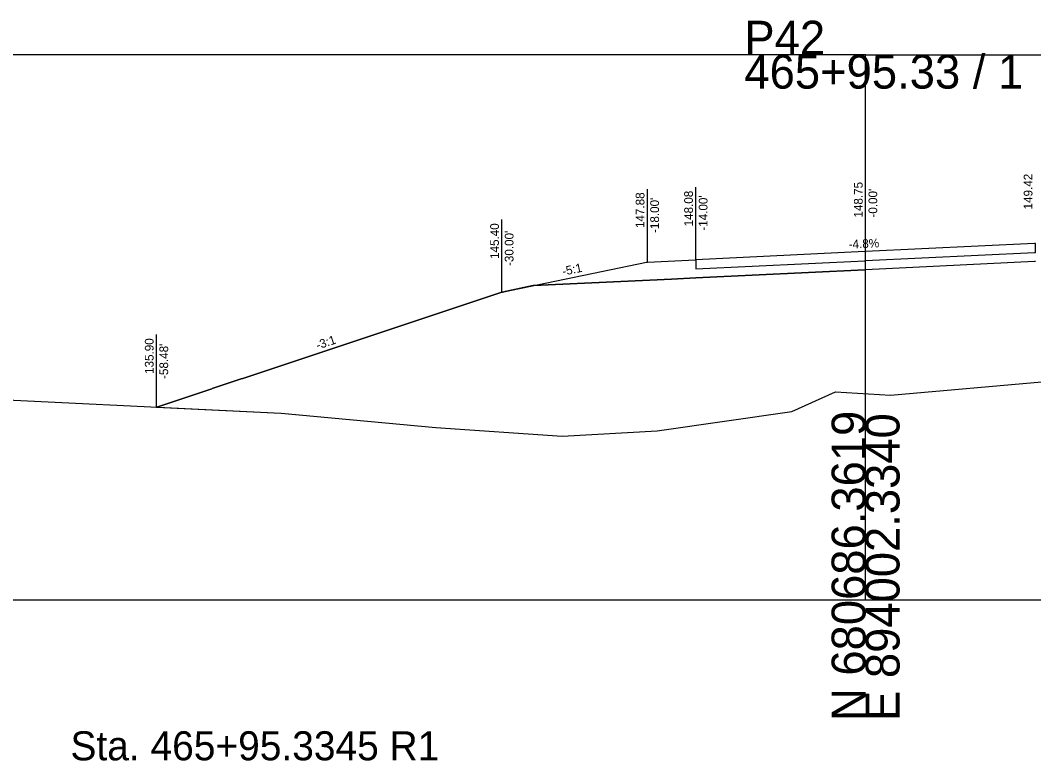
# Model space of a CAD drawing. Extents: x -26 to 4403, y -13 to 9578.
# Drawn here: x 1180.3 to 1263.9, y 6986.7 to 7047.8 of the extents above; entities that cross this region are included whole.
import ezdxf

# ---------------------------------------------------------------- set-up
doc = ezdxf.new("R2010")
doc.units = 0
for name, color, linetype in [('_CIVIL_CONSTRUCTION', 7, 'Continuous'), ('CONST_DCH', 7, 'Continuous'), ('CONST_LV3', 7, 'Continuous'), ('Draft_XS_Text', 7, 'Continuous'), ('DTM_CORRIDOR', 7, 'Continuous'), ('DTM_TEMP_DROP', 7, 'Continuous'), ('DTM_X_GROUND', 7, 'Continuous'), ('SLOPE_STAKES_FILL', 7, 'Continuous'), ('XS_CELL', 7, 'Continuous'), ('XS_M_SHAPES_EARTHWORK', 7, 'Continuous'), ('XS_P_ASPHALT', 7, 'Continuous'), ('XS_P_GROUND', 7, 'Continuous'), ('XS_P_SHOULDER', 7, 'Continuous'), ('XS_P_SUBGRADE_GRANULAR', 7, 'Continuous'), ('XS_P_TX_CLEARZONE', 7, 'Continuous'), ('XS_P_TX_FS_BS', 7, 'Continuous')]:
    doc.layers.add(name, color=color, linetype=linetype)

msp = doc.modelspace()

# ---------------------------------------------------------------- linework, layer by layer
at = {"layer": 'CONST_LV3'}
msp.add_lwpolyline([(1220, 7025.397), (1220.013, 7025.399), (1222.586, 7025.933)], dxfattribs=at)
at = {"layer": 'DTM_X_GROUND'}
msp.add_lwpolyline([(1172.393, 7016.843), (1201.803, 7015.398), (1214.564, 7014.215), (1224.971, 7013.522), (1232.816, 7013.949), (1243.916, 7015.546), (1247.514, 7017.177), (1252.067, 7016.906), (1267.338, 7018.231), (1284.701, 7020.032), (1288.812, 7020.146), (1295.897, 7020.771), (1296.81, 7020.815), (1306.145, 7020.771), (1331.242, 7020.749), (1362.053, 7020.566), (1388.429, 7020.524), (1400, 7020.43)], dxfattribs=at)
at = {"layer": 'XS_CELL'}
for p, q in [((1250, 7000), (1250, 7045)), ((1000, 7000), (1250, 7000)), ((1250, 7000), (1400, 7000))]:
    msp.add_line(p, q, dxfattribs=at)
at = {"layer": 'XS_M_SHAPES_EARTHWORK'}
msp.add_lwpolyline([(1263.924, 7027.917), (1250, 7027.249), (1249.924, 7027.245), (1236, 7026.577), (1235.989, 7026.576), (1234, 7026.481), (1222.649, 7025.936), (1222.586, 7025.933), (1220.013, 7025.399), (1220, 7025.397), (1198.648, 7018.28), (1198.511, 7018.234), (1196.103, 7017.432), (1196.09, 7017.427), (1191.629, 7015.941), (1191.604, 7015.932), (1191.518, 7015.904), (1201.803, 7015.398), (1214.564, 7014.215), (1224.971, 7013.522), (1232.816, 7013.949), (1243.916, 7015.546), (1247.514, 7017.177), (1252.067, 7016.906), (1267.338, 7018.231)], dxfattribs=at)
at = {"layer": 'XS_P_ASPHALT'}
msp.add_lwpolyline([(1249.924, 7028.745), (1236, 7028.077), (1236, 7028.073), (1236, 7027.327), (1249.924, 7027.995), (1250, 7027.999), (1263.924, 7028.667), (1264, 7028.671), (1264, 7029.417), (1264, 7029.421), (1263.924, 7029.417), (1250, 7028.749), (1249.924, 7028.745)], dxfattribs=at)
at = {"layer": 'XS_P_GROUND'}
for q in [(1035, 7045), (1380, 7045)]:
    msp.add_line((1250, 7045), q, dxfattribs=at)
msp.add_lwpolyline([(1191.518, 7015.904), (1191.604, 7015.932), (1191.629, 7015.941), (1196.09, 7017.427), (1196.103, 7017.432), (1198.511, 7018.234), (1198.648, 7018.28), (1220, 7025.397), (1231.935, 7027.871), (1232, 7027.885)], dxfattribs=at)
at = {"layer": 'XS_P_SHOULDER'}
msp.add_lwpolyline([(1232, 7027.885), (1235.978, 7028.076), (1236, 7028.077)], dxfattribs=at)
at = {"layer": 'XS_P_SUBGRADE_GRANULAR'}
for points in [[(1236, 7026.577), (1249.924, 7027.245), (1250, 7027.249)], [(1264, 7027.921), (1263.924, 7027.917), (1250, 7027.249)], [(1222.586, 7025.933), (1222.649, 7025.936), (1234, 7026.481), (1235.989, 7026.576), (1236, 7026.577)]]:
    msp.add_lwpolyline(points, dxfattribs=at)
at = {"layer": 'XS_P_TX_CLEARZONE'}
for p, q in [((1250, 7028.749), (1250, 7034.749)), ((1250, 7028.749), (1250, 7034.749)), ((1250, 7028.749), (1250, 7034.749)), ((1250, 7028.749), (1250, 7034.749)), ((1250, 7028.749), (1250, 7034.749)), ((1250, 7028.749), (1250, 7034.749)), ((1232, 7027.885), (1232, 7033.885)), ((1232, 7027.885), (1232, 7033.885)), ((1232, 7027.885), (1232, 7033.885)), ((1236, 7028.077), (1236, 7034.077)), ((1236, 7028.077), (1236, 7034.077)), ((1236, 7028.077), (1236, 7034.077)), ((1220, 7025.397), (1220, 7031.397)), ((1220, 7025.397), (1220, 7031.397)), ((1220, 7025.397), (1220, 7031.397)), ((1220, 7025.397), (1220, 7031.397)), ((1220, 7025.397), (1220, 7031.397)), ((1220, 7025.397), (1220, 7031.397)), ((1191.518, 7015.904), (1191.518, 7021.904)), ((1191.518, 7015.904), (1191.518, 7021.904)), ((1191.518, 7015.904), (1191.518, 7021.904)), ((1191.518, 7015.904), (1191.518, 7021.904)), ((1191.518, 7015.904), (1191.518, 7021.904)), ((1191.518, 7015.904), (1191.518, 7021.904)), ((1191.518, 7015.904), (1191.518, 7021.904)), ((1191.518, 7015.904), (1191.518, 7021.904)), ((1191.518, 7015.904), (1191.518, 7021.904))]:
    msp.add_line(p, q, dxfattribs=at)

# ---------------------------------------------------------------- texts
at = {"layer": '_CIVIL_CONSTRUCTION'}
for p in [(1235.961, 7028.017), (1249.961, 7028.689)]:
    msp.add_text('X', height=0.12, dxfattribs=at).set_placement(p)
at = {"layer": 'CONST_DCH'}
msp.add_text('X', height=0.12, dxfattribs=at).set_placement((1191.479, 7015.844))
at = {"layer": 'Draft_XS_Text'}
msp.add_text('Sta. 465+95.3345 R1', height=2.4, dxfattribs=at).set_placement((1184.42, 6986.75))
at = {"layer": 'DTM_CORRIDOR'}
msp.add_text('X', height=0.12, dxfattribs=at).set_placement((1191.479, 7015.844))
at = {"layer": 'DTM_TEMP_DROP'}
msp.add_text('X', height=0.12, dxfattribs=at).set_placement((1231.961, 7027.825))
at = {"layer": 'SLOPE_STAKES_FILL'}
msp.add_text('X', height=0.12, dxfattribs=at).set_placement((1219.961, 7025.337))
at = {"layer": 'XS_CELL'}
for s, p in [('P42', (1240, 7045)), ('465+95.33 / 1', (1240, 7042.2))]:
    msp.add_text(s, height=2.8, dxfattribs=at).set_placement(p)
for s, p in [('N 680686.3619', (1250, 6990)), ('E 894002.3340', (1252.8, 6990))]:
    msp.add_text(s, height=2.8, rotation=90, dxfattribs=at).set_placement(p)
at = {"layer": 'XS_P_TX_CLEARZONE'}
for s, p in [('149.42', (1263.76, 7032.225)), ('149.42', (1263.76, 7032.225)), ('149.42', (1263.76, 7032.225)), ('149.42', (1263.76, 7032.225)), ('149.42', (1263.76, 7032.225)), ('149.42', (1263.76, 7032.225)), ('148.75', (1249.76, 7031.553)), ('148.75', (1249.76, 7031.553)), ('148.75', (1249.76, 7031.553)), ('148.75', (1249.76, 7031.553)), ('148.75', (1249.76, 7031.553)), ('148.75', (1249.76, 7031.553)), ("-0.00'", (1250.96, 7031.553)), ("-0.00'", (1250.96, 7031.553)), ("-0.00'", (1250.96, 7031.553)), ("-0.00'", (1250.96, 7031.553)), ("-0.00'", (1250.96, 7031.553)), ("-0.00'", (1250.96, 7031.553)), ('147.88', (1231.76, 7030.689)), ('147.88', (1231.76, 7030.689)), ('147.88', (1231.76, 7030.689)), ("-18.00'", (1232.96, 7030.281)), ("-18.00'", (1232.96, 7030.281)), ("-18.00'", (1232.96, 7030.281)), ('148.08', (1235.76, 7030.824)), ('148.08', (1235.76, 7030.824)), ('148.08', (1235.76, 7030.824)), ("-14.00'", (1236.96, 7030.473)), ("-14.00'", (1236.96, 7030.473)), ("-14.00'", (1236.96, 7030.473)), ('145.40', (1219.76, 7028.138)), ('145.40', (1219.76, 7028.138)), ('145.40', (1219.76, 7028.138)), ('145.40', (1219.76, 7028.138)), ('145.40', (1219.76, 7028.138)), ('145.40', (1219.76, 7028.138)), ("-30.00'", (1220.96, 7027.555)), ("-30.00'", (1220.96, 7027.555)), ("-30.00'", (1220.96, 7027.555)), ("-30.00'", (1220.96, 7027.555)), ("-30.00'", (1220.96, 7027.555)), ("-30.00'", (1220.96, 7027.555)), ('135.90', (1191.278, 7018.645)), ('135.90', (1191.278, 7018.645)), ('135.90', (1191.278, 7018.645)), ('135.90', (1191.278, 7018.645)), ('135.90', (1191.278, 7018.645)), ('135.90', (1191.278, 7018.645)), ('135.90', (1191.278, 7018.645)), ('135.90', (1191.278, 7018.645)), ('135.90', (1191.278, 7018.645)), ("-58.48'", (1192.478, 7018.232)), ("-58.48'", (1192.478, 7018.232)), ("-58.48'", (1192.478, 7018.232)), ("-58.48'", (1192.478, 7018.232)), ("-58.48'", (1192.478, 7018.232)), ("-58.48'", (1192.478, 7018.232)), ("-58.48'", (1192.478, 7018.232)), ("-58.48'", (1192.478, 7018.232)), ("-58.48'", (1192.478, 7018.232))]:
    msp.add_text(s, height=0.72, rotation=90, dxfattribs=at).set_placement(p)
at = {"layer": 'XS_P_TX_FS_BS'}
for s, rotation, p in [('-4.8%', 2.74809, (1248.619, 7028.983)), ('-4.8%', 2.74809, (1248.619, 7028.983)), ('-4.8%', 2.74809, (1248.619, 7028.983)), ('-5:1', 11.71335, (1225.051, 7026.75)), ('-5:1', 11.71335, (1225.051, 7026.75)), ('-5:1', 11.71335, (1225.051, 7026.75)), ('-3:1', 18.43323, (1204.804, 7020.648)), ('-3:1', 18.43323, (1204.804, 7020.648)), ('-3:1', 18.43323, (1204.804, 7020.648))]:
    msp.add_text(s, height=0.72, rotation=rotation, dxfattribs=at).set_placement(p)

doc.saveas('drawing.dxf')
